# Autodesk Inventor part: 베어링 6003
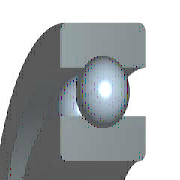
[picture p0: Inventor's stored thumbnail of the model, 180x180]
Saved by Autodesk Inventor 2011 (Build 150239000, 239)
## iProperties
IsCustomPart: 1
Company: 한국ATC센터
Created: 2014-07
Part Number: 베어링 6003
Material: 강, 연강
Description: 깊은 그루브 볼 베어링
Document SubType Name: Modeling
Standard: KS B 2023
Designer: KYOUNG IL JANG
Standards Organization: KS
Language: ko-KR
Size Designation: 6003 - 17 x 35 x 10
Categories: <MemberInstance><Categories><Category DisplayName="샤프트 부품" InternalName="7f7aeb1f-a693-4053-b835-cee3144e0d98" Mnemonic="SHFT"><Category DisplayName="베어링" Inter
Density: 1 g/cm^3
Author: KYOUNG IL JANG
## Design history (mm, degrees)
revolve "본체" stored, may be unused: angle "d6" = 90 deg
revolve "볼" stored, may be unused: angle "d7" = 90 deg
pattern_circular "IDS_ARRAYBALL[SIMPL:T]" dims angle "d3" = 360 deg
body "Solid1"
sketch "스케치" dims "d0" = 4.68 (= -0.26 x WD + 0.26 x BD)
  geometry: L1 (2.66, 13)-(7.34, 13); L2 (5, 13)-(5, 10.66); L3 (5, 13)-(5, 15.34); L4 (3.261, 11.434)-(0, 11.434); L5 (0, 8.5)-(10, 8.5); L6 (3.261, 14.566)-(0, 14.566); L7 (0, 17.5)-(10, 17.5); L8 (10, 8.5)-(10, 11.434); L9 (6.739, 11.434)-(10, 11.434); L10 (6.739, 14.566)-(10, 14.566); L11 (10, 17.5)-(10, 14.566); L12 (-1.4, 0)-(8.4, 0) reference; L13 (0, -0.3)-(0, 5.3) reference
  constraints: 22 end point, 4 point on line, 2 collinear, 2 perpendicular, 2 symmetric about line, 1 midpoint, 1 parallel, 14 other
  dimensions: "d9" = 17 diameter of L5 L12 (= WD); "d11" = 35 diameter of L7 L12 (= BD); "d12" = 10 distance between parallel lines of L8 L13 (= KB); "d13" = 22.868 diameter of L9 L12 (= 0.326 x BD + 0.674 x WD)
fillet "모깎기1" dims "d1" = 0.3 (= KRS)
other parameters: "WD" = 17 [user parameter; used in 5 equation terms], "BD" = 35 [user parameter; used in 5 equation terms], "KB" = 10 [user parameter; used in 1 equation term], "KRS" = 0.3 [user parameter; used in 1 equation term], "d4" = 0, "d5" = 0, "d8" = 0, "d14" = 0, "d15" = 0, "BBA" = 0 [user parameter], "BC0" = 3250000 [user parameter], "BC" = 6050000 [user parameter], "BR" = 17.5 (= 0.5 x BD) [user parameter], "WR" = 8.5 (= 0.5 x WD) [user parameter]
